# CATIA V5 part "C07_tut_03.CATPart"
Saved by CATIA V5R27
Part number: Part1
Bounding box of the stored display mesh (mm): x 0 to 108, y -52.5 to 52.5, z -52.5 to 52.5
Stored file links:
  E:\_Deepak\2017_Deepak\CATIA\Resources\Tutorial Files\Tutorials\c07_catia_v5_6r2016_tut\C07_tut_03.CATPart
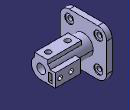
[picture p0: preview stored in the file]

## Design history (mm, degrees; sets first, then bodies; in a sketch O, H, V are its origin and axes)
Body1 (main body)
  Sketch1 on yz-plane, origin (0, 0, 0), H (0, 1, 0), V (0, 0, 1)
    line L1 (52.5, 32.5) -> (52.5, -32.5)
    line L2 (32.5, -52.5) -> (-32.5, -52.5)
    line L3 (-52.5, -32.5) -> (-52.5, 32.5)
    line L4 (-32.5, 52.5) -> (32.5, 52.5)
    point P1 (52.5, 52.5)
    point P2 (52.5, -52.5)
    point P3 (-52.5, -52.5)
    arc A1 centre (32.5, 32.5) radius 20 from (52.5, 32.5) to (32.5, 52.5) ccw
    arc A2 centre (32.5, -32.5) radius 20 from (52.5, -32.5) to (32.5, -52.5) cw
    arc A3 centre (-32.5, -32.5) radius 20 from (-32.5, -52.5) to (-52.5, -32.5) cw
    arc A4 centre (-32.5, 32.5) radius 20 from (-52.5, 32.5) to (-32.5, 52.5) cw
    distance P1 P2 = 105
    radius A1 = 20
    distance P2 P3 = 105
    radius A2 = 20
    radius A3 = 20
    radius A4 = 20
    vertical: L1 V, L3 V
    horizontal: L2 H, L4 H
    equidistance: L1 L3 O, L2 L4 O
    coincidence: L1 P1, L4 P1, L1 P2, L2 P2, L2 P3, L3 P3
    tangency: A1 L1, A1 L4, A2 L1, A2 L2, A3 L2, A3 L3, A4 L3, A4 L4
  Pad1: profile Sketch1, direction (1, 0, 0), length 12
  Sketch2 on face of Pad1, origin (12, 0, 0), H (0, 1, 0), V (0, 0, 1)
    circle A1 centre (0, 0) radius 22
    radius A1 = 22
  Pad2: profile Sketch2, direction (1, 0, 0), length 96
  Sketch3 on face of Pad2, origin (108, 0, 0), H (0, 1, 0), V (0, 0, 1)
    point P1 (-15, 16.0935)
    line L1 (-15, 16.0935) -> (-15, 25)
    line L2 (-15, 25) -> (15, 25)
    line L3 (15, 25) -> (15, 16.0935)
    point P4 (15, 16.0935)
    axis line L4 (0, 0) -> (0, 25)
    point P5 (0, 25)
    reference projected circle E1 centre (0, 0) radius 22 from edge [face of Pad2 | face of Pad2]
    reference projected circle E2 centre (0, 0) radius 22 from edge [face of Pad2 | face of Pad2]
    projected circle E3 centre (0, 0) radius 22 from edge [face of Pad2 | face of Pad2]
    projected arc E4 centre (0, 0) radius 22 from (15, 16.0935) to (-15, 16.0935) ccw from edge [face of Pad2 | face of Pad2]
    length L2 = 30
    distance H L2 = 25
    vertical: L1 V, L3 V, L4 V
    horizontal: L2 H
    midpoint: P5 L2
    coincidence: P4 E1, P1 E2
  Pad3: profile Sketch3, direction (-1, 0, 0), length 76
  Sketch4 on face of Pad2, origin (108, 0, 0), H (0, 1, 0), V (0, 0, 1)
    point P1 (0, -22)
    line L1 (0, -22) -> (32, -22)
    line L2 (32, -22) -> (32, 8)
    line L3 (32, 8) -> (20.4939, 8)
    point P4 (20.4939, 8)
    reference projected circle E1 centre (0, 0) radius 22 from edge of Pad2
    reference projected circle E2 centre (0, 0) radius 22 from edge [face of Pad2 | face of Pad2]
    reference projected circle E3 centre (0, 0) radius 22 from edge [face of Pad2 | face of Pad2]
    projected arc E4 centre (0, 0) radius 22 from (-15, 16.0935) to (15, 16.0935) ccw from edge of Pad3
    projected arc E5 centre (0, 0) radius 22 from (0, -22) to (20.4939, 8) ccw from edge of Pad3
    length L2 = 30
    distance V L2 = 32
    coincidence: P1 V, P4 E1, P1 E2
    horizontal: L1 H, L3 H
    vertical: L2 V
    tangency: L1 E3
  Pad4: profile Sketch4, direction (-1, 0, 0), length 57
  Sketch5 on face of Pad2, origin (108, 0, 0), H (0, 1, 0), V (0, 0, 1)
    line L1 (17, 2) -> (25, 2)
    line L2 (25, 2) -> (25, -17)
    line L3 (25, -17) -> (17, -17)
    line L4 (17, -17) -> (17, 2)
    length L2 = 19
    length L1 = 8
    distance H L1 = 2
    distance V L2 = 25
    horizontal: L1 H, L3 H
    vertical: L2 V, L4 V
  Pocket1: profile Sketch5, direction (-1, 0, 0), length 50
  Sketch6 on face of Pad2, origin (108, 0, 0), H (0, 1, 0), V (0, 0, 1)
    point P1 (0, 0)
    coincidence: P1 O
  Hole1: placed by Sketch6, at (108, 0, 0) direction (-1, 0, 0), diameter 20, up to end face of Pad1
  Sketch7 on face of Pad3, origin (90.7325, -5.9449, 25), H (1, 0, 0), V (0, 1, 0)
    point P1 (1.2675, 5.9449)
    reference projected line E1 (17.2675, -9.0551) -> (-58.7325, -9.0551) from edge [face of Pad3 | face of Pad3]
    reference projected line E2 (17.2675, 20.9449) -> (17.2675, -9.0551) from edge [face of Pad3 | face of Pad3]
    distance P1 E1 = 15
    distance P1 E2 = 16
  Hole2: placed by Sketch7, at (92, 0, 25) direction (0, 0, -1), diameter 12, depth 33.0037, threaded, thread diameter 13.2, thread depth 10, pitch 1
  RectPattern1: of Hole2, direction 1 instances 2, spacing 44, along edge [face of Pad3 | face of Pad3]
  Sketch8 on face of Pad4, origin (86.2721, 32, -2.7131), H (1, 0, 0), V (0, 0, -1)
    point P1 (10.7279, 4.2869)
    reference projected line E1 (21.7279, 19.2869) -> (-35.2721, 19.2869) from edge [face of Pad4 | face of Pad4]
    reference projected line E2 (21.7279, 19.2869) -> (21.7279, -10.7131) from edge [face of Pad4 | face of Pad4]
    distance P1 E1 = 15
    distance E2 P1 = 11
  Hole3: placed by Sketch8, at (97, 32, -7) direction (0, -1, 0), diameter 10, through (limit type 6)
  RectPattern2: of Hole3, direction 1 instances 2, spacing 25, along edge [face of Pad4 | face of Pad4], direction 2 instances 2, spacing 76
  Sketch9 on face of Pad1, origin (12, -36.1764, 22.8739), H (0, 1, 0), V (0, 0, 1)
    point P1 (3.6764, -55.3739)
    reference projected line E1 (-16.3236, 9.6261) -> (-16.3236, -55.3739) from edge [face of Pad1 | face of Pad1]
    reference projected line E2 (3.6764, -75.3739) -> (68.6764, -75.3739) from edge [face of Pad1 | face of Pad1]
    distance P1 E1 = 20
    distance E2 P1 = 20
  Hole4: placed by Sketch9, at (12, -32.5, -32.5) direction (-1, 0, 0), diameter 10, through (limit type 3), counterbore diameter 20, counterbore depth 2
  RectPattern3: of Hole4, direction 1 instances 2, spacing 66, along edge [face of Pad1 | face of Pad1], direction 2 instances 2, spacing 66, along edge [face of Pad1 | face of Pad1] reversed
